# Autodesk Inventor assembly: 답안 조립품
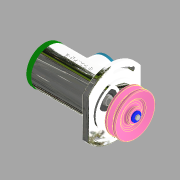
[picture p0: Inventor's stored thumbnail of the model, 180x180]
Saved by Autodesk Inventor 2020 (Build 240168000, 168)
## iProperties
Created: 2022-05
Part Number: 답안 조립품
Document SubType Name: Assembly
Designer: Student
Author: Student
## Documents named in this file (21)
- C:\Users\Student\Desktop\7205056V1017\답안 조립품.iam
- C:\Users\Student\Desktop\7205056V1017\답안본체.ipt
- C:\Users\Student\Desktop\7205056V1017\탑 커버.ipt
- C:\Users\Student\Desktop\7205056V1017\베어링 6202.ipt
- C:\Users\Student\Desktop\7205056V1017\멈춤링 35 x 1.6.ipt
- C:\Users\Student\Desktop\7205056V1017\멈춤링 15 x 1.ipt
- C:\Users\Student\Desktop\7205056V1017\축.ipt
- C:\Users\Student\Desktop\7205056V1017\부시1.ipt
- C:\Users\Student\Desktop\7205056V1017\부시2.ipt
- C:\Users\Student\Desktop\7205056V1017\와셔 10 x 21.ipt
- C:\Users\Student\Desktop\7205056V1017\너트 M10.ipt
- C:\Users\Student\Desktop\7205056V1017\사이드 커버.ipt
- 사이드 커버.ipt
- C:\Users\Student\Desktop\7205056V1017\오일 실 15 x 30 x 7.ipt
- C:\Users\Student\Desktop\7205056V1017\키 4 x 4.ipt
- C:\Users\Student\Desktop\7205056V1017\V-벨트풀리.ipt
- C:\Users\Student\Desktop\7205056V1017\멈춤나사 M3.ipt
- C:\Users\Student\Desktop\7205056V1017\볼트 M4 x 10.ipt
- C:\Users\Student\Desktop\7205056V1017\와셔 4 x 16.ipt
- C:\Users\Student\Desktop\7205056V1017\와셔 3 x 6.ipt
- C:\Users\Student\Desktop\7205056V1017\십자볼트 M3 x 10.ipt
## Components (2 placed, 2 different names)
1. V-벨트풀리:1
2. ISO 4017 M4 x 10:1
